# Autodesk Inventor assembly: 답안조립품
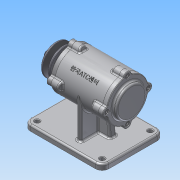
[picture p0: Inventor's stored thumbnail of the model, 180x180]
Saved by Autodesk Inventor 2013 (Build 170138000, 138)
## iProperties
Created: 2015-12
Part Number: 답안조립품
Document SubType Name: Assembly
Designer: Administrator
Author: Administrator
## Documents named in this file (11)
- C:\Users\Administrator\Desktop\451208V1020\답안조립품.iam
- C:\Users\Administrator\Desktop\451208V1020\본체.ipt
- C:\Users\Administrator\Desktop\451208V1020\축.ipt
- C:\Users\Administrator\Desktop\451208V1020\베어링 6204.ipt
- C:\Users\Administrator\Desktop\451208V1020\키(4 x 4 x 12).ipt
- C:\Users\Administrator\Desktop\451208V1020\커버2.ipt
- C:\Users\Administrator\Desktop\451208V1020\볼트 M4 x 12.ipt
- C:\Users\Administrator\Desktop\451208V1020\커버.ipt
- C:\Users\Administrator\Desktop\451208V1020\오일실.ipt
- C:\Users\Administrator\Desktop\451208V1020\V-벨트풀리.ipt
- C:\Users\Administrator\Desktop\451208V1020\너트 M12x1.25.ipt
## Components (6 placed, 5 different names)
1. KS B 2023 6204 - 20 x 47 x 14:1
2. KS B 2023 6204 - 20 x 47 x 14:2
3. KS B 1311 (I) 4 x 4 x 12:1 — 각도:1, 각도:4
4. KS B 2804 D D - 20 32 8:1
5. V-벨트풀리:1 — 각도:4
6. KS B 1012 클래스 1 일반 - 미터 M12x1.25:1 — 각도:5
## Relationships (3: Angle 3)
- 각도:1 [Angle]: KS B 1311 (I) 4 x 4 x 12:1
- 각도:4 [Angle]: KS B 1311 (I) 4 x 4 x 12:1 ↔ V-벨트풀리:1
- 각도:5 [Angle]: KS B 1012 클래스 1 일반 - 미터 M12x1.25:1
